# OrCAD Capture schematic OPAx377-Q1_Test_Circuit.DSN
size A; title: OPAx377-Q1 Low-Noise, Low Quiescent Current, Precision; rev: 1.0; note: Datasheet: SBOS797A EVM: NA
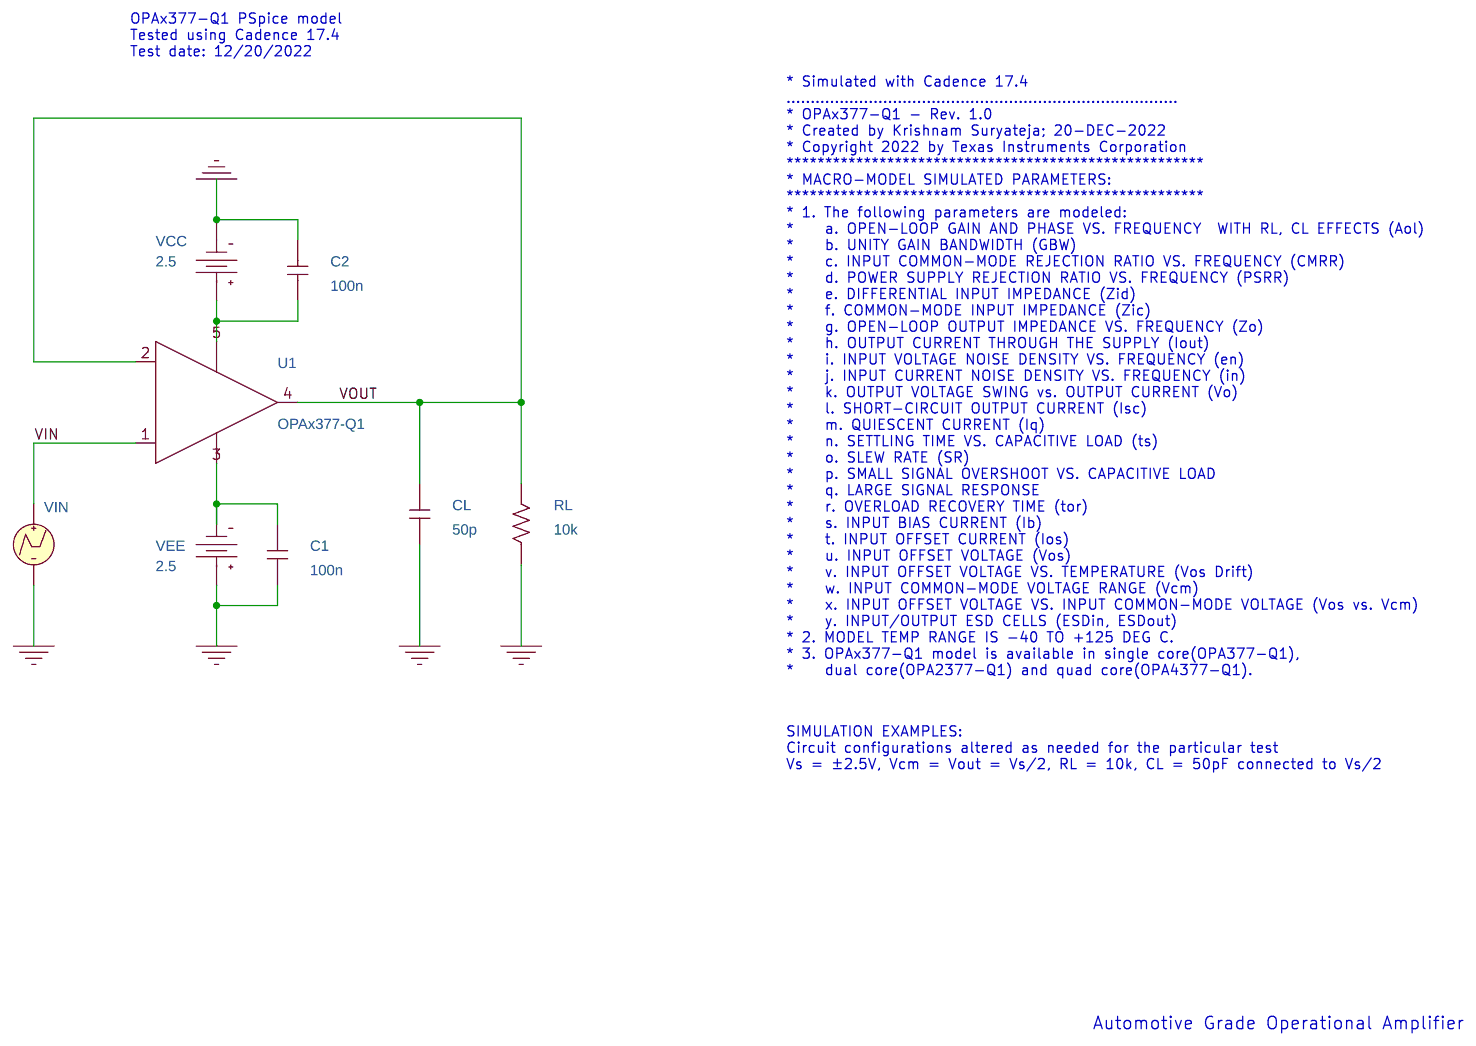
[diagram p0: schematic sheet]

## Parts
C1  100n  [RAD/CK05]
C2  100n  [RAD/CK05]
CL  50p  [RAD/CK05]
RL  10k  [AX/RC05]
U1  OPAx377-Q1
VCC  VDC
VEE  VDC
VIN  VPWL

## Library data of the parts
C1 C2 CL = C
RL = R
U1 = OPAx377-Q1
VCC VEE = VDC: DC: 2.5
VIN = VPWL: AC: 1; T1: 0; T2: 0.1n; T3: 1u; T4: 1.01u; T5: 2u; T6: 2.01u; T7: 3u; T8: 3.01u; V1: 0; V2: 0.1; V3: 0.1; V4: -0.1; V5: -0.1; V6: 0.1; V7: 0.1; V8: -0.1

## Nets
VIN: U1.1(+) VIN.1(+)
0: C1.1 C2.2 CL.1 RL.1 VCC.1(-) VEE.0(+) VIN.2(-)
VOUT: CL.2 RL.2 U1.2(-) U1.4(OUT)
N14309457: C2.1 U1.5(V+) VCC.0(+)
N14309611: C1.2 U1.3(V-) VEE.1(-)

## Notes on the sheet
- OPAx377-Q1 PSpice model
  Tested using Cadence 17.4
  Test date: 12/20/2022
- * Simulated with Cadence 17.4
  .................................................................................
  * OPAx377-Q1 - Rev. 1.0
  * Created by Krishnam Suryateja; 20-DEC-2022
  * Copyright 2022 by Texas Instruments Corporation
  ******************************************************
  * MACRO-MODEL SIMULATED PARAMETERS:
  ******************************************************
  * 1. The following parameters are modeled:
  *    a. OPEN-LOOP GAIN AND PHASE VS. FREQUENCY  WITH RL, CL EFFECTS (Aol)
  *    b. UNITY GAIN BANDWIDTH (GBW)
  *    c. INPUT COMMON-MODE REJECTION RATIO VS. FREQUENCY (CMRR)
  *    d. POWER SUPPLY REJECTION RATIO VS. FREQUENCY (PSRR)
  *    e. DIFFERENTIAL INPUT IMPEDANCE (Zid)
  *    f. COMMON-MODE INPUT IMPEDANCE (Zic)
  *    g. OPEN-LOOP OUTPUT IMPEDANCE VS. FREQUENCY (Zo)
  *    h. OUTPUT CURRENT THROUGH THE SUPPLY (Iout)
  *    i. INPUT VOLTAGE NOISE DENSITY VS. FREQUENCY (en)
  *    j. INPUT CURRENT NOISE DENSITY VS. FREQUENCY (in)
  *    k. OUTPUT VOLTAGE SWING vs. OUTPUT CURRENT (Vo)
  *    l. SHORT-CIRCUIT OUTPUT CURRENT (Isc)
  *    m. QUIESCENT CURRENT (Iq)
  *    n. SETTLING TIME VS. CAPACITIVE LOAD (ts)
  *    o. SLEW RATE (SR)
  *    p. SMALL SIGNAL OVERSHOOT VS. CAPACITIVE LOAD
  *    q. LARGE SIGNAL RESPONSE
  *    r. OVERLOAD RECOVERY TIME (tor)
  *    s. INPUT BIAS CURRENT (Ib)
  *    t. INPUT OFFSET CURRENT (Ios)
  *    u. INPUT OFFSET VOLTAGE (Vos)
  *    v. INPUT OFFSET VOLTAGE VS. TEMPERATURE (Vos Drift)
  *    w. INPUT COMMON-MODE VOLTAGE RANGE (Vcm)
  *    x. INPUT OFFSET VOLTAGE VS. INPUT COMMON-MODE VOLTAGE (Vos vs. Vcm)
  *    y. INPUT/OUTPUT ESD CELLS (ESDin, ESDout)
  * 2. MODEL TEMP RANGE IS -40 TO +125 DEG C.
  * 3. OPAx377-Q1 model is available in single core(OPA377-Q1),
  *    dual core(OPA2377-Q1) and quad core(OPA4377-Q1).
- SIMULATION EXAMPLES:
  Circuit configurations altered as needed for the particular test
  Vs = ±2.5V, Vcm = Vout = Vs/2, RL = 10k, CL = 50pF connected to Vs/2
- Automotive Grade Operational Amplifier
